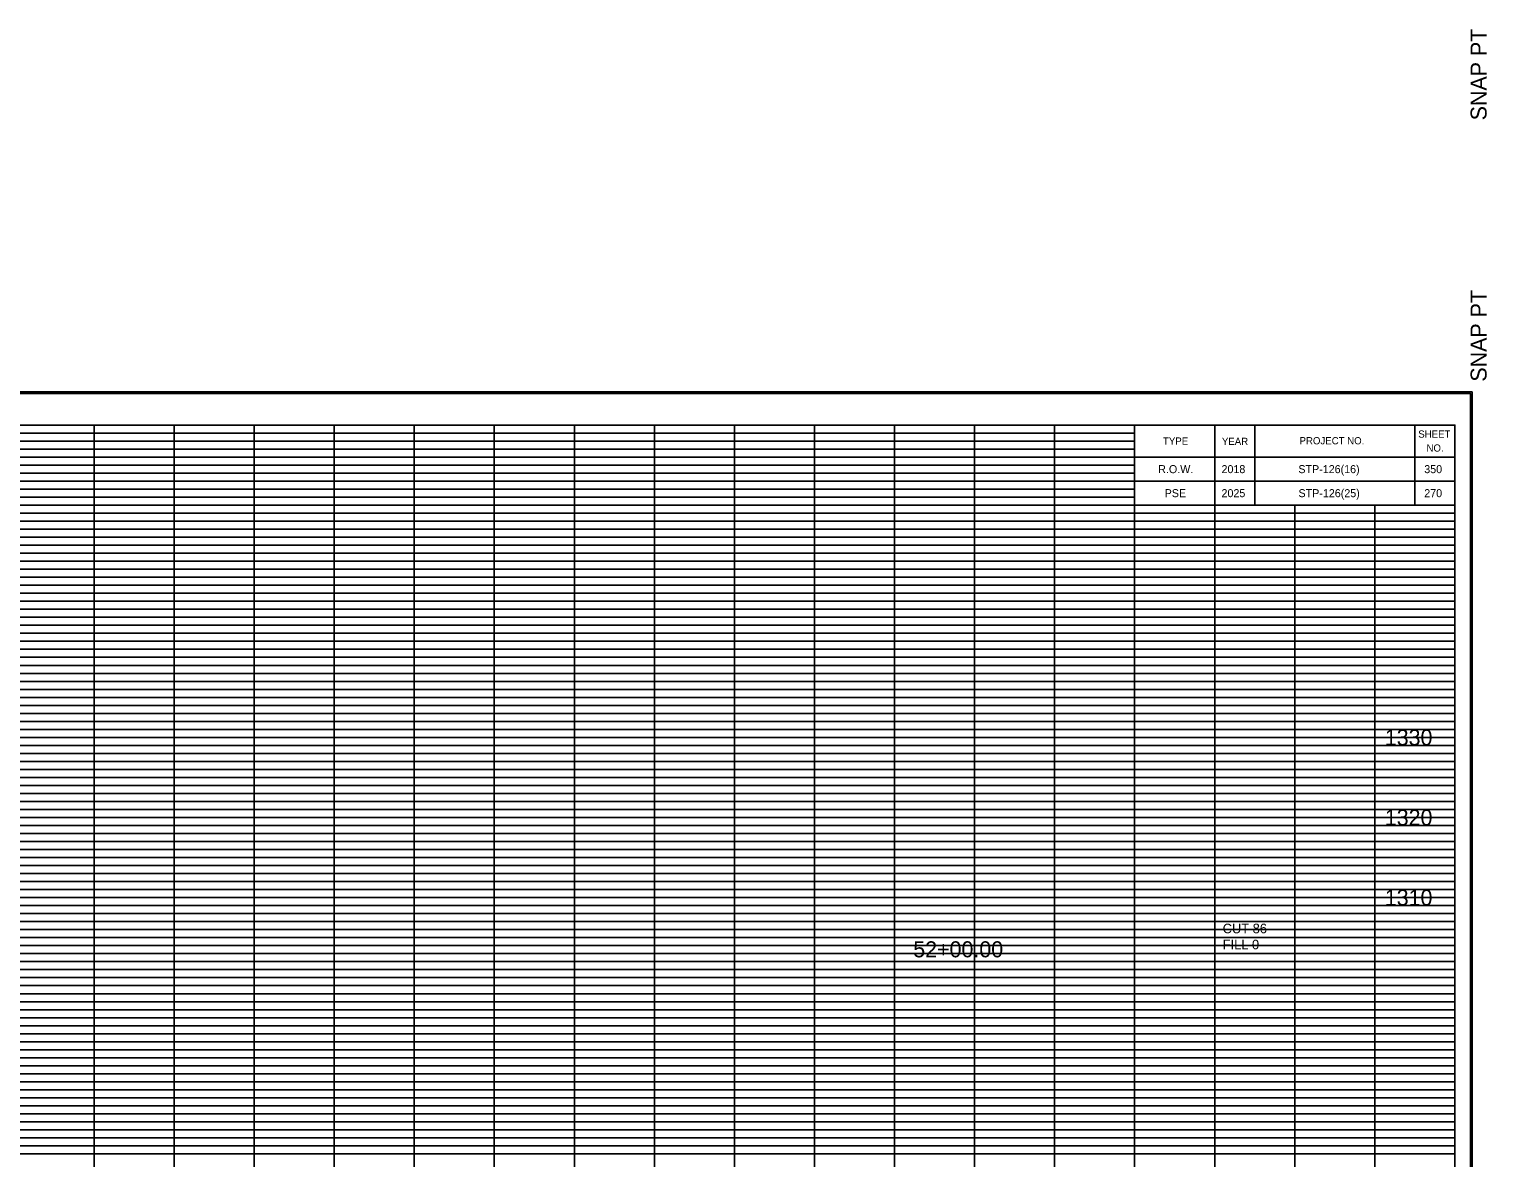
# Model space of a CAD drawing. Extents: x 130 to 1324, y -58 to 2657.
# Drawn here: x 1141.9 to 1324, y 1118.5 to 1259.4 of the extents above; entities that cross this region are included whole.
import ezdxf

# ---------------------------------------------------------------- set-up
doc = ezdxf.new("R2010")
doc.units = 0
for name, color, linetype in [('DESIGN - SCRATCH - User 1', 7, 'Continuous'), ('DESIGN - SCRATCH - User 2', 7, 'Continuous'), ('DESIGN - SHEET - Corner Text', 7, 'Continuous'), ('DESIGN - SHEET - Light Grid', 7, 'Continuous'), ('DESIGN - SHEET - Linework', 7, 'Continuous'), ('DESIGN - SHEET - Plot Shape', 7, 'Continuous'), ('DESIGN - TYPICAL - Finished Grade and Subgrade', 7, 'Continuous'), ('DESIGN - TYPICAL - Text', 7, 'Continuous')]:
    doc.layers.add(name, color=color, linetype=linetype)

# ---------------------------------------------------------------- blocks, each defined once
blk = doc.blocks.new('XSTSHT')
at = {"layer": 'DESIGN - SCRATCH - User 1'}
for p, q in [((28.5, 20.45), (28.5, 20.45)), ((29.24, 20.45), (29.24, 20.45)), ((30.49, 20.45), (30.49, 20.45)), ((31.74, 20.45), (31.74, 20.45)), ((28.5, 20.15), (28.5, 20.15)), ((29.24, 20.15), (29.24, 20.15)), ((30.49, 20.15), (30.49, 20.15)), ((31.74, 20.15), (31.74, 20.15))]:
    blk.add_line(p, q, dxfattribs=at)
at = {"layer": 'DESIGN - SHEET - Light Grid'}
for p, q in [((8, 20.9), (16, 20.9)), ((8, 20.8), (16, 20.8)), ((16, 20.9), (24, 20.9)), ((16, 20.8), (24, 20.8)), ((24, 20.9), (28, 20.9)), ((24, 20.8), (28, 20.8)), ((8, 20.7), (16, 20.7)), ((8, 20.6), (16, 20.6)), ((16, 20.7), (24, 20.7)), ((16, 20.6), (24, 20.6)), ((24, 20.7), (28, 20.7)), ((24, 20.6), (28, 20.6)), ((8, 20.5), (16, 20.5)), ((8, 20.4), (16, 20.4)), ((16, 20.5), (24, 20.5)), ((16, 20.4), (24, 20.4)), ((24, 20.5), (28, 20.5)), ((24, 20.4), (28, 20.4)), ((8, 20.3), (16, 20.3)), ((16, 20.3), (24, 20.3)), ((24, 20.3), (28, 20.3)), ((8, 20.2), (16, 20.2)), ((8, 20.1), (16, 20.1)), ((16, 20.2), (24, 20.2)), ((16, 20.1), (24, 20.1)), ((24, 20.2), (28, 20.2)), ((24, 20.1), (28, 20.1)), ((8, 19.9), (16, 19.9)), ((16, 19.9), (24, 19.9)), ((24, 19.9), (32, 19.9)), ((8, 19.8), (16, 19.8)), ((8, 19.7), (16, 19.7)), ((16, 19.8), (24, 19.8)), ((16, 19.7), (24, 19.7)), ((24, 19.8), (32, 19.8)), ((24, 19.7), (32, 19.7)), ((8, 19.6), (16, 19.6)), ((8, 19.5), (16, 19.5)), ((16, 19.6), (24, 19.6)), ((16, 19.5), (24, 19.5)), ((24, 19.6), (32, 19.6)), ((24, 19.5), (32, 19.5)), ((8, 19.4), (16, 19.4)), ((16, 19.4), (24, 19.4)), ((24, 19.4), (32, 19.4)), ((8, 19.3), (16, 19.3)), ((8, 19.2), (16, 19.2)), ((16, 19.3), (24, 19.3)), ((16, 19.2), (24, 19.2)), ((24, 19.3), (32, 19.3)), ((24, 19.2), (32, 19.2)), ((8, 19.1), (16, 19.1)), ((16, 19.1), (24, 19.1)), ((24, 19.1), (32, 19.1)), ((8, 18.9), (16, 18.9)), ((8, 18.8), (16, 18.8)), ((16, 18.9), (24, 18.9)), ((16, 18.8), (24, 18.8)), ((24, 18.9), (32, 18.9)), ((24, 18.8), (32, 18.8)), ((8, 18.7), (16, 18.7)), ((8, 18.6), (16, 18.6)), ((16, 18.7), (24, 18.7)), ((16, 18.6), (24, 18.6)), ((24, 18.7), (32, 18.7)), ((24, 18.6), (32, 18.6)), ((8, 18.5), (16, 18.5)), ((8, 18.4), (16, 18.4)), ((16, 18.5), (24, 18.5)), ((16, 18.4), (24, 18.4)), ((24, 18.5), (32, 18.5)), ((24, 18.4), (32, 18.4)), ((8, 18.3), (16, 18.3)), ((16, 18.3), (24, 18.3)), ((24, 18.3), (32, 18.3)), ((8, 18.2), (16, 18.2)), ((8, 18.1), (16, 18.1)), ((16, 18.2), (24, 18.2)), ((16, 18.1), (24, 18.1)), ((24, 18.2), (32, 18.2)), ((24, 18.1), (32, 18.1)), ((8, 17.9), (16, 17.9)), ((16, 17.9), (24, 17.9)), ((24, 17.9), (32, 17.9)), ((8, 17.8), (16, 17.8)), ((8, 17.7), (16, 17.7)), ((16, 17.8), (24, 17.8)), ((16, 17.7), (24, 17.7)), ((24, 17.8), (32, 17.8)), ((24, 17.7), (32, 17.7)), ((8, 17.6), (16, 17.6)), ((8, 17.5), (16, 17.5)), ((16, 17.6), (24, 17.6)), ((16, 17.5), (24, 17.5)), ((24, 17.6), (32, 17.6)), ((24, 17.5), (32, 17.5)), ((8, 17.4), (16, 17.4)), ((16, 17.4), (24, 17.4)), ((24, 17.4), (32, 17.4)), ((8, 17.3), (16, 17.3)), ((8, 17.2), (16, 17.2)), ((16, 17.3), (24, 17.3)), ((16, 17.2), (24, 17.2)), ((24, 17.3), (32, 17.3)), ((24, 17.2), (32, 17.2)), ((8, 17.1), (16, 17.1)), ((16, 17.1), (24, 17.1)), ((24, 17.1), (32, 17.1)), ((8, 16.9), (16, 16.9)), ((8, 16.8), (16, 16.8)), ((16, 16.9), (24, 16.9)), ((16, 16.8), (24, 16.8)), ((24, 16.9), (32, 16.9)), ((24, 16.8), (32, 16.8)), ((8, 16.7), (16, 16.7)), ((8, 16.6), (16, 16.6)), ((16, 16.7), (24, 16.7)), ((16, 16.6), (24, 16.6)), ((24, 16.7), (32, 16.7)), ((24, 16.6), (32, 16.6)), ((8, 16.5), (16, 16.5)), ((8, 16.4), (16, 16.4)), ((16, 16.5), (24, 16.5)), ((16, 16.4), (24, 16.4)), ((24, 16.5), (32, 16.5)), ((24, 16.4), (32, 16.4)), ((8, 16.3), (16, 16.3)), ((16, 16.3), (24, 16.3)), ((24, 16.3), (32, 16.3)), ((8, 16.2), (16, 16.2)), ((8, 16.1), (16, 16.1)), ((16, 16.2), (24, 16.2)), ((16, 16.1), (24, 16.1)), ((24, 16.2), (32, 16.2)), ((24, 16.1), (32, 16.1)), ((8, 15.9), (16, 15.9)), ((16, 15.9), (24, 15.9)), ((24, 15.9), (32, 15.9)), ((8, 15.8), (16, 15.8)), ((8, 15.7), (16, 15.7)), ((16, 15.8), (24, 15.8)), ((16, 15.7), (24, 15.7)), ((24, 15.8), (32, 15.8)), ((24, 15.7), (32, 15.7)), ((8, 15.6), (16, 15.6)), ((8, 15.5), (16, 15.5)), ((16, 15.6), (24, 15.6)), ((16, 15.5), (24, 15.5)), ((24, 15.6), (32, 15.6)), ((24, 15.5), (32, 15.5)), ((8, 15.4), (16, 15.4)), ((8, 15.3), (16, 15.3)), ((16, 15.4), (24, 15.4)), ((16, 15.3), (24, 15.3)), ((24, 15.4), (32, 15.4)), ((24, 15.3), (32, 15.3)), ((8, 15.2), (16, 15.2)), ((16, 15.2), (24, 15.2)), ((24, 15.2), (32, 15.2)), ((8, 15.1), (16, 15.1)), ((16, 15.1), (24, 15.1)), ((24, 15.1), (32, 15.1)), ((8, 14.9), (16, 14.9)), ((8, 14.8), (16, 14.8)), ((16, 14.9), (24, 14.9)), ((16, 14.8), (24, 14.8)), ((24, 14.9), (32, 14.9)), ((24, 14.8), (32, 14.8)), ((8, 14.7), (16, 14.7)), ((8, 14.6), (16, 14.6)), ((16, 14.7), (24, 14.7)), ((16, 14.6), (24, 14.6)), ((24, 14.7), (32, 14.7)), ((24, 14.6), (32, 14.6)), ((8, 14.5), (16, 14.5)), ((8, 14.4), (16, 14.4)), ((16, 14.5), (24, 14.5)), ((16, 14.4), (24, 14.4)), ((24, 14.5), (32, 14.5)), ((24, 14.4), (32, 14.4)), ((8, 14.3), (16, 14.3)), ((16, 14.3), (24, 14.3)), ((24, 14.3), (32, 14.3)), ((8, 14.2), (16, 14.2)), ((8, 14.1), (16, 14.1)), ((16, 14.2), (24, 14.2)), ((16, 14.1), (24, 14.1)), ((24, 14.2), (32, 14.2)), ((24, 14.1), (32, 14.1)), ((8, 13.9), (16, 13.9)), ((16, 13.9), (24, 13.9)), ((24, 13.9), (32, 13.9)), ((8, 13.8), (16, 13.8)), ((8, 13.7), (16, 13.7)), ((16, 13.8), (24, 13.8)), ((16, 13.7), (24, 13.7)), ((24, 13.8), (32, 13.8)), ((24, 13.7), (32, 13.7)), ((8, 13.6), (16, 13.6)), ((8, 13.5), (16, 13.5)), ((16, 13.6), (24, 13.6)), ((16, 13.5), (24, 13.5)), ((24, 13.6), (32, 13.6)), ((24, 13.5), (32, 13.5)), ((8, 13.4), (16, 13.4)), ((8, 13.3), (16, 13.3)), ((16, 13.4), (24, 13.4)), ((16, 13.3), (24, 13.3)), ((24, 13.4), (32, 13.4)), ((24, 13.3), (32, 13.3)), ((8, 13.2), (16, 13.2)), ((16, 13.2), (24, 13.2)), ((24, 13.2), (32, 13.2)), ((8, 13.1), (16, 13.1)), ((16, 13.1), (24, 13.1)), ((24, 13.1), (32, 13.1)), ((8, 12.9), (16, 12.9)), ((8, 12.8), (16, 12.8)), ((16, 12.9), (24, 12.9)), ((16, 12.8), (24, 12.8)), ((24, 12.9), (32, 12.9)), ((24, 12.8), (32, 12.8)), ((8, 12.7), (16, 12.7)), ((8, 12.6), (16, 12.6)), ((16, 12.7), (24, 12.7)), ((16, 12.6), (24, 12.6)), ((24, 12.7), (32, 12.7)), ((24, 12.6), (32, 12.6)), ((8, 12.5), (16, 12.5)), ((8, 12.4), (16, 12.4)), ((16, 12.5), (24, 12.5)), ((16, 12.4), (24, 12.4)), ((24, 12.5), (32, 12.5)), ((24, 12.4), (32, 12.4)), ((8, 12.3), (16, 12.3)), ((16, 12.3), (24, 12.3)), ((24, 12.3), (32, 12.3)), ((8, 12.2), (16, 12.2)), ((8, 12.1), (16, 12.1)), ((16, 12.2), (24, 12.2)), ((16, 12.1), (24, 12.1)), ((24, 12.2), (32, 12.2)), ((24, 12.1), (32, 12.1)), ((8, 11.9), (16, 11.9)), ((16, 11.9), (24, 11.9)), ((24, 11.9), (32, 11.9))]:
    blk.add_line(p, q, dxfattribs=at)
at = {"layer": 'DESIGN - SHEET - Linework'}
for p, q in [((-1.823, 21.414), (32.217, 21.414)), ((32.217, 21.414), (32.217, -0.414)), ((15, 0), (15, 21)), ((16, 0), (16, 21)), ((17, 0), (17, 21)), ((18, 0), (18, 21)), ((19, 0), (19, 21)), ((20, 0), (20, 21)), ((21, 0), (21, 21)), ((22, 0), (22, 21)), ((23, 0), (23, 21)), ((24, 0), (24, 21)), ((25, 0), (25, 21)), ((26, 0), (26, 21)), ((27, 0), (27, 21)), ((0, 20), (28, 20)), ((28, 0), (28, 20)), ((29, 0), (29, 20)), ((30, 0), (30, 20)), ((31, 0), (31, 20)), ((0, 19), (32, 19)), ((0, 18), (32, 18)), ((0, 17), (32, 17)), ((0, 16), (32, 16)), ((0, 15), (32, 15)), ((0, 14), (32, 14)), ((0, 13), (32, 13)), ((0, 12), (32, 12))]:
    blk.add_line(p, q, dxfattribs=at)
for points in [[(0, 21), (0, 0), (32, 0), (32, 21), (0, 21)], [(28, 21), (28, 20), (32, 20), (32, 21), (31.5, 21), (31.5, 20), (29.5, 20), (29.5, 21), (29, 21), (29, 20), (32, 20), (28, 20), (28, 20.3), (32, 20.3), (32, 20.6), (28, 20.6)]]:
    blk.add_lwpolyline(points, dxfattribs=at)
at = {"layer": 'DESIGN - SHEET - Plot Shape'}
for points in [[(-1.803, 21.394), (32.197, 21.394), (32.197, -0.394), (-1.803, -0.394)], [(-0.85, 21), (32, 21), (32, -0.25), (-0.85, -0.25)]]:
    blk.add_lwpolyline(points, close=True, dxfattribs=at)
at = {"layer": 'DESIGN - SHEET - Corner Text'}
for s, p in [('  SNAP PT', (32.397, 21.394)), ('SNAP PT  ', (32.397, -2.194))]:
    blk.add_text(s, height=0.2, rotation=90, dxfattribs=at).set_placement(p)
for s, p in [('TYPE', (28.354, 20.756)), ('YEAR', (29.09, 20.752)), ('PROJECT NO.', (30.06, 20.76)), ('SHEET', (31.543, 20.843)), ('NO.', (31.646, 20.669))]:
    blk.add_text(s, height=0.09, dxfattribs=at).set_placement(p)

msp = doc.modelspace()

# ---------------------------------------------------------------- linework, layer by layer
at = {"layer": 'DESIGN - SCRATCH - User 2'}
msp.add_lwpolyline([(1010, 1140), (1310, 1140), (1310, 1180), (1010, 1180)], close=True, dxfattribs=at)
at = {"layer": 'DESIGN - SHEET - Plot Shape'}
msp.add_lwpolyline([(991.5, 997.5), (1320, 997.5), (1320, 1210), (991.5, 1210)], close=True, dxfattribs=at)

# ---------------------------------------------------------------- block references
at = {"layer": 'DESIGN - TYPICAL - Finished Grade and Subgrade', "xscale": 10, "yscale": 10}
for p in [(1000, 1270), (1000, 1000)]:
    msp.add_blockref('XSTSHT', p, dxfattribs=at)

# ---------------------------------------------------------------- texts
at = {"layer": 'DESIGN - SHEET - Corner Text'}
for s, height, p in [('R.O.W.', 1, (1282.94, 1204)), ('2018', 1, (1290.85, 1204)), ('STP-126(16)', 1, (1300.45, 1204)), ('350', 1, (1316.18, 1204)), ('PSE', 1, (1283.75, 1201)), ('2025', 1, (1290.85, 1201)), ('STP-126(25)', 1, (1300.47, 1201)), ('270', 1, (1316.18, 1201)), ('1330', 2, (1311.25, 1170)), ('1320', 2, (1311.25, 1160)), ('1310', 2, (1311.25, 1150)), ('52+00.00', 2, (1252.34, 1143.54))]:
    msp.add_text(s, height=height, dxfattribs=at).set_placement(p)
at = {"layer": 'DESIGN - TYPICAL - Text'}
for s, p in [('CUT 86', (1291, 1146.54)), ('FILL 0', (1291, 1144.54))]:
    msp.add_text(s, height=1.2, dxfattribs=at).set_placement(p)

doc.saveas('drawing.dxf')
